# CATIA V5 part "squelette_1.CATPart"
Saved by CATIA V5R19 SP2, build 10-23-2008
Part number: squelette_1
Publications: "Point.3", "Droite.2", "Point.4", "Droite.3", "Plan yz"
Bounding box of the stored display mesh (mm): x -10 to 10, y 0 to 27, z 0 to 0
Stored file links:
  M:\EU_thinkMotion\IAO_2010\iao\IAO_MMS_Groupe2\IAO_MMS_Groupe2\sdubois\sdubois\sdubois\IAO_mecanisme\squelette_1.CATPart
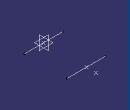
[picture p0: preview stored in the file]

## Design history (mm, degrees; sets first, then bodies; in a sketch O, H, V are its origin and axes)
Point1: (0, 22, 0)
Point2: (0, 0, 0)
Set1
  Line1: type Normal, RefPoint Point2, RefSkin yz-plane, Start 10, End -10
  Line2: type Normal, RefPoint Point1, RefSkin yz-plane, Start 10, End -10
  Point3: (0, 27, 0)
Body1 (main body)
